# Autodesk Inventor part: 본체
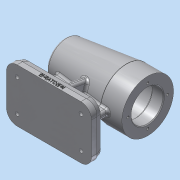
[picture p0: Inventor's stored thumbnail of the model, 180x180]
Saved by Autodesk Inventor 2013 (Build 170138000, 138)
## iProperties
Created: 2017-01
Part Number: 본체
Material: 알루미늄 6061
Document SubType Name: Modeling
Designer: dgall
Density: 2.71 g/cm^3
Mass: 795.033 g
Surface Area: 661.674 cm^2
Volume: 293.37 cm^3
Author: dgall
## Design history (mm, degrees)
sketch "스케치1"
  geometry: L1 (-56, 0)-(56, 0); L2 (-52.27, 24.144)-(28, 34); L3 (28, 34)-(56, 34); L4 (56, 34)-(56, 0); L5 (-56, -60)-(56, -60); L6 (56, -60)-(56, -67); L7 (56, -67)-(-56, -67); L8 (-56, -67)-(-56, -60); L9 (-50, 0)-(-50, 10.5); L10 (-50, 10.5)-(-47, 10.5); L11 (-47, 10.5)-(-47, 16); L12 (-47, 16)-(-43, 16); L13 (-43, 16)-(-43, 17.5); L14 (-43, 17.5)-(-25, 17.5); L15 (-25, 17.5)-(-25, 21); L16 (-25, 21)-(-13, 21); L17 (-13, 21)-(-13, 24); L18 (-13, 24)-(41, 24); L19 (41, 24)-(41, 21); L20 (41, 21)-(56, 21); A1 r 80 centre (24, 0) between (-52.27, 24.144) and (-56, 0); 3 further points
  constraints: 40 end point, 14 parallel, 3 midpoint, 3 perpendicular, 2 horizontal, 2 point on circle, 2 point on line, 1 centre point, 1 coincident, 1 horizontal alignment, 1 vertical alignment
  dimensions: "d0" = 112 distance of L1.start L1.end; "d2" = 28 distance of L2.end L3.end; "d3" = 7 deg angle of L2 L3; "d4" = 80 radius of A1; "d5" = 68 diameter of L3 L1; "d6" = 7 distance of L5.end L6.end; "d7" = 67 distance from line of L1.start L7; "d8" = 112 distance of L6.end L7.end; "d9" = 15 distance of L19.end L20.end; "d10" = 54 distance of L17.end L18.end; "d11" = 12 distance of L15.end L16.end; "d12" = 18 distance of L13.end L14.end; "d13" = 4 distance of L11.end L12.end; "d14" = 3 distance of L9.end L10.end; "d15" = 21 diameter of L10 L1; "d16" = 32 diameter of L12 L1; "d17" = 35 diameter of L14 L1; "d18" = 42 diameter of L16 L1; "d19" = 48 diameter of L18 L1; "d20" = 42 diameter of L20 L1
revolve "회전1" stored, may be unused: angle "d21" = 90 deg
extrude "돌출1" join sketch "스케치1" stored distance "d22" = 70; taper "d23" = 0 deg
feature "면 기울기1" dims angle "d24" = -15 deg
fillet "모깎기1" dims "d44" = 14
sketch "스케치2"
  geometry: L1 (112, 0)-(112, -70) reference; L2 (0, 0)-(112, 0) reference; L3 (0, 0)-(0, -70) reference; L4 (112, -70)-(0, -70) reference; 1 further point
extrude "돌출2" join sketch "스케치2" distance "d25" = 7; taper "d26" = 0 deg
sketch "스케치3"
  geometry: L1 (0, 66.249)-(108.249, 66.249) reference; L2 (16.124, 37.124)-(50.124, 37.124); L3 (50.124, 37.124)-(50.124, 56.124); L4 (50.124, 56.124)-(58.124, 56.124); L5 (58.124, 56.124)-(58.124, 37.124); L6 (58.124, 37.124)-(92.124, 37.124); L7 (92.124, 37.124)-(92.124, 29.124); L8 (92.124, 29.124)-(58.124, 29.124); L9 (58.124, 29.124)-(58.124, 10.124); L10 (58.124, 10.124)-(50.124, 10.124); L11 (50.124, 10.124)-(50.124, 29.124); L12 (50.124, 29.124)-(16.124, 29.124); L13 (16.124, 29.124)-(16.124, 37.124); L14 (-1.876, 11.647)-(-1.876, 54.601) reference; L15 (96.601, 68.124)-(11.647, 68.124) reference; 6 further points
  constraints: 24 end point, 8 parallel, 3 equal length, 3 horizontal alignment, 3 vertical alignment, 2 collinear, 2 midpoint, 2 perpendicular
  dimensions: "d27" = 8 distance of L3.end L4.end; "d29" = 18 distance between parallel lines of L13 L14; "d30" = 12 distance between parallel lines of L4 L15
extrude "돌출3" join sketch "스케치3" stored distance "d31" = 7; taper "d32" = 0 deg
sketch "스케치4"
  geometry: C1 r 21 at (0, 0) reference; 1 further point
  constraints: 1 vertical alignment
  dimensions: "d33" = 26 distance of point (0, 26) C1.centre
hole "구멍1" sketch "스케치4" at (0, 26) diameter "d34" = 3.242; stored, may be unused: countersink angle "d38" = 90 deg, drill point angle "d40" = 118 deg; dims "d35" = 8, "d36" = 4, "d37" = 2, "d39" = 11
fillet "모깎기2" dims "d45" = 14
sketch "스케치7"
  geometry: L1 (4.375, 54.124)-(1.488, 49.124); L2 (1.488, 49.124)-(-4.285, 49.124); L3 (-4.285, 49.124)-(-7.172, 54.124); L4 (-7.172, 54.124)-(-4.285, 59.124); L5 (-4.285, 59.124)-(1.488, 59.124); L6 (1.488, 59.124)-(4.375, 54.124); L7 (-15.399, 12.124)-(-15.399, 54.124) reference; L8 (82.601, 68.124)-(-1.399, 68.124) reference; C1 r 5 at (-1.399, 54.124); 7 further points; 1 other entity
  constraints: 12 end point, 3 coincident, 1 centre point, 1 horizontal alignment, 1 tangent, 14 other
  dimensions: "d70" = 14 distance from line of point (-1.399, 54.124) L7; "d71" = 10 diameter of C1; "d72" = 14 distance from line of C1.centre L8 (= d70)
extrude "돌출4" cut sketch "스케치7" distance "d73" = 4; taper "d74" = 0 deg
sketch "스케치8"
  geometry: L1 (-15.399, 12.124)-(-15.399, 54.124) reference; L2 (82.601, 68.124)-(-1.399, 68.124) reference; 2 further points
  dimensions: "d81" = 14 distance from line of point (-1.399, 54.124) L1; "d82" = 14 distance from line of point (-1.399, 54.124) L2
hole "구멍3" sketch "스케치8" at (-1.399, 54.124) diameter "d83" = 5; stored, may be unused: countersink angle "d87" = 90 deg, drill point angle "d89" = 118 deg; dims "d84" = 8, "d85" = 10, "d86" = 4, "d88" = 11
feature "면 기울기2" dims angle "d53" = 10 deg
chamfer "모따기1" distance "d54" = 1; stored, may be unused: second distance "d55" = 2, angle "d56" = 45 deg
fillet "모깎기3" dims "d57" = 0.3, "d58" = 3
fillet "모깎기4" dims "d59" = 3
fillet "모깎기5" dims "d60" = 3
fillet "모깎기6" dims "d61" = 3
fillet "모깎기7" dims "d62" = 1
node "작업 평면1"
sketch "스케치6"
  geometry: L1 (56, -74)-(42, -74) reference; 2 further points
  constraints: 1 vertical alignment, 1 other
  dimensions: "d64" = 4 distance from line of point (0, -70) L1
feature "엠보싱1" sketch "스케치6" dims "d0" = 112, "d2" = 28, "d3" = 7 deg, "d4" = 80, "d5" = 68, "d6" = 7, "d7" = 67, "d8" = 112, "d9" = 15, "d10" = 54, "d11" = 12, "d12" = 18, "d13" = 4, "d14" = 3, "d15" = 21, "d16" = 32, "d17" = 35, "d18" = 42, "d19" = 48, "d20" = 42, "d65" = 0.5, "d66" = 0
node "솔리드1"
pattern_circular "원형 패턴1" dims angle "d42" = 360 deg
pattern_linear "직사각형 패턴1" dims "d77" = 42, "d80" = 84
pattern_linear "직사각형 패턴2" dims "d92" = 42, "d95" = 84
